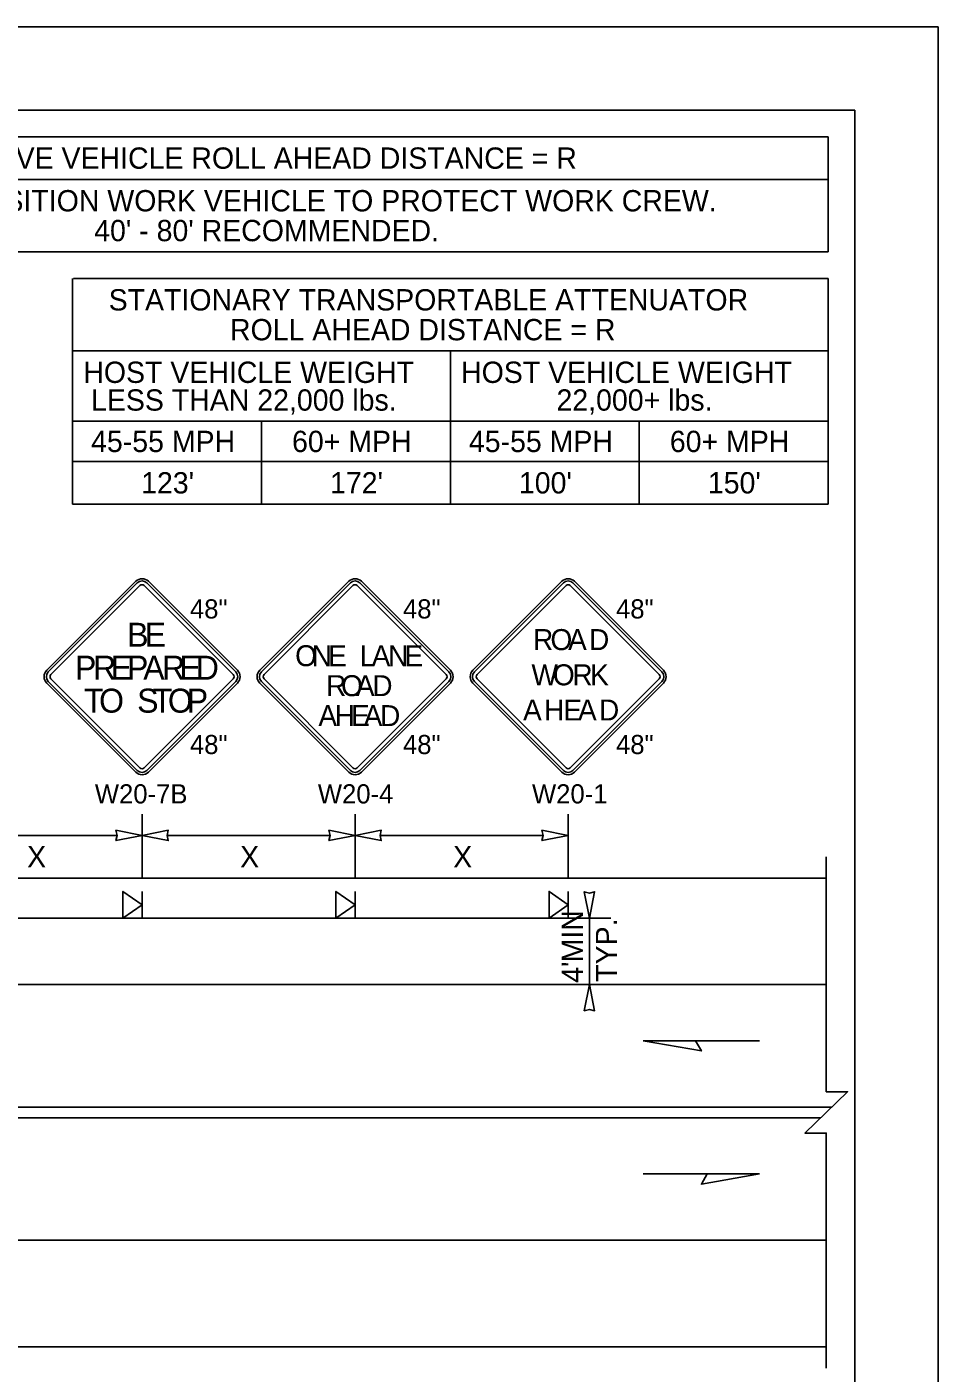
# Model space of a CAD drawing. Extents: x 99999.1 to 100095.7, y 99995 to 100010.7.
# Drawn here: x 100052.64 to 100056.06, y 100005.63 to 100010.69 of the extents above; entities that cross this region are included whole.
import ezdxf

# ---------------------------------------------------------------- set-up
doc = ezdxf.new("R2010")
doc.units = 0
for name, color, linetype in [('RD_ED_ShoulderPavedEdge', 7, 'Continuous'), ('RD_MK_LineDblYellowCenter', 7, 'Continuous'), ('RD_MK_LineEdgeWhite', 7, 'Continuous'), ('SH_GI_PlotLimits', 7, 'Continuous'), ('SH_GI_SheetBorder', 7, 'Continuous'), ('SH_TI_Tables', 7, 'Continuous'), ('TR_SN_ConstructionSigns', 7, 'Continuous'), ('TR_WZ_PortableSignMountBlk-Org', 7, 'Continuous'), ('TR_WZ_WorkZoneDetails', 7, 'Continuous'), ('TR_WZ_WorkZoneTextCurrent', 7, 'Continuous')]:
    doc.layers.add(name, color=color, linetype=linetype)

msp = doc.modelspace()

# ---------------------------------------------------------------- linework, layer by layer
at = {"layer": 'RD_ED_ShoulderPavedEdge'}
for p, q in [((100040.1076, 100007.4923), (100055.6424, 100007.4923)), ((100040.1076, 100005.7323), (100055.6424, 100005.7323))]:
    msp.add_line(p, q, dxfattribs=at)
at = {"layer": 'RD_MK_LineDblYellowCenter'}
for p, q in [((100052.2733, 100006.6323), (100055.6631, 100006.6323)), ((100052.2733, 100006.5923), (100055.6218, 100006.5923))]:
    msp.add_line(p, q, dxfattribs=at)
at = {"layer": 'RD_MK_LineEdgeWhite'}
for p, q in [((100040.1076, 100007.0923), (100055.6424, 100007.0923)), ((100040.1076, 100006.1323), (100055.6424, 100006.1323))]:
    msp.add_line(p, q, dxfattribs=at)
at = {"layer": 'SH_GI_PlotLimits'}
msp.add_lwpolyline([(100039.0625, 99999.6875), (100056.0625, 99999.6875), (100056.0625, 100010.6875), (100039.0625, 100010.6875)], close=True, dxfattribs=at)
at = {"layer": 'SH_GI_SheetBorder'}
for p, q in [((100040, 100010.375), (100055.75, 100010.375)), ((100055.75, 100010.375), (100055.75, 100000))]:
    msp.add_line(p, q, dxfattribs=at)
at = {"layer": 'SH_TI_Tables'}
for p, q in [((100051.4347, 100010.275), (100055.65, 100010.275)), ((100055.65, 100009.843), (100055.65, 100010.275)), ((100051.4347, 100010.115), (100055.65, 100010.115)), ((100051.4347, 100009.843), (100055.65, 100009.843)), ((100052.8126, 100008.896), (100052.8126, 100009.743)), ((100052.8156, 100009.743), (100055.65, 100009.743)), ((100055.65, 100008.896), (100055.65, 100009.743)), ((100052.8126, 100009.471), (100055.65, 100009.471)), ((100054.2313, 100008.896), (100054.2313, 100009.471)), ((100052.8126, 100009.2069), (100054.2313, 100009.2069)), ((100053.5219, 100008.896), (100053.5219, 100009.2069)), ((100054.2313, 100009.2069), (100055.65, 100009.2069)), ((100054.9406, 100008.896), (100054.9406, 100009.2069)), ((100052.8126, 100009.056), (100054.2313, 100009.056)), ((100054.2313, 100009.056), (100055.65, 100009.056)), ((100052.8126, 100008.896), (100055.65, 100008.896))]:
    msp.add_line(p, q, dxfattribs=at)
at = {"layer": 'TR_SN_ConstructionSigns'}
for p, q in [((100053.0495, 100008.6062), (100052.7154, 100008.2721)), ((100053.0555, 100008.6002), (100052.7213, 100008.2661)), ((100052.7313, 100008.2561), (100053.0654, 100008.5903)), ((100053.0813, 100008.5903), (100053.4154, 100008.2561)), ((100053.4254, 100008.2661), (100053.0912, 100008.6002)), ((100053.4313, 100008.2721), (100053.0972, 100008.6062)), ((100053.8495, 100008.6062), (100053.5154, 100008.2721)), ((100053.8555, 100008.6002), (100053.5213, 100008.2661)), ((100053.5313, 100008.2561), (100053.8654, 100008.5903)), ((100053.8813, 100008.5903), (100054.2154, 100008.2561)), ((100054.2254, 100008.2661), (100053.8912, 100008.6002)), ((100054.2313, 100008.2721), (100053.8972, 100008.6062)), ((100054.6495, 100008.6062), (100054.3154, 100008.2721)), ((100054.6555, 100008.6002), (100054.3213, 100008.2661)), ((100054.3313, 100008.2561), (100054.6654, 100008.5903)), ((100054.6813, 100008.5903), (100055.0154, 100008.2561)), ((100055.0254, 100008.2661), (100054.6912, 100008.6002)), ((100055.0313, 100008.2721), (100054.6972, 100008.6062)), ((100053.0654, 100007.9061), (100052.7313, 100008.2402)), ((100053.4154, 100008.2402), (100053.0813, 100007.9061)), ((100053.8654, 100007.9061), (100053.5313, 100008.2402)), ((100054.2154, 100008.2402), (100053.8813, 100007.9061)), ((100054.6654, 100007.9061), (100054.3313, 100008.2402)), ((100055.0154, 100008.2402), (100054.6813, 100007.9061)), ((100052.7154, 100008.2243), (100053.0495, 100007.8902)), ((100052.7213, 100008.2303), (100053.0555, 100007.8962)), ((100053.0912, 100007.8962), (100053.4254, 100008.2303)), ((100053.0972, 100007.8902), (100053.4313, 100008.2243)), ((100053.5154, 100008.2243), (100053.8495, 100007.8902)), ((100053.5213, 100008.2303), (100053.8555, 100007.8962)), ((100053.8912, 100007.8962), (100054.2254, 100008.2303)), ((100053.8972, 100007.8902), (100054.2313, 100008.2243)), ((100054.3154, 100008.2243), (100054.6495, 100007.8902)), ((100054.3213, 100008.2303), (100054.6555, 100007.8962)), ((100054.6912, 100007.8962), (100055.0254, 100008.2303)), ((100054.6972, 100007.8902), (100055.0313, 100008.2243))]:
    msp.add_line(p, q, dxfattribs=at)
for centre, radius, start, end in [((100053.0733, 100008.5823), 0.0338, 45, 135), ((100053.0733, 100008.5823), 0.0253, 45, 135), ((100053.0733, 100008.5823), 0.0113, 45, 135), ((100053.8733, 100008.5823), 0.0338, 45, 135), ((100053.8733, 100008.5823), 0.0253, 45, 135), ((100053.8733, 100008.5823), 0.0113, 45, 135), ((100054.6733, 100008.5823), 0.0338, 45, 135), ((100054.6733, 100008.5823), 0.0253, 45, 135), ((100054.6733, 100008.5823), 0.0113, 45, 135), ((100052.7392, 100008.2482), 0.0338, 135, 225), ((100052.7392, 100008.2482), 0.0253, 135, 225), ((100052.7392, 100008.2482), 0.0113, 135, 225), ((100053.4075, 100008.2482), 0.0113, 315, 45), ((100053.4075, 100008.2482), 0.0253, 315, 45), ((100053.4075, 100008.2482), 0.0338, 315, 45), ((100053.5392, 100008.2482), 0.0338, 135, 225), ((100053.5392, 100008.2482), 0.0253, 135, 225), ((100053.5392, 100008.2482), 0.0113, 135, 225), ((100054.2075, 100008.2482), 0.0113, 315, 45), ((100054.2075, 100008.2482), 0.0253, 315, 45), ((100054.2075, 100008.2482), 0.0338, 315, 45), ((100054.3392, 100008.2482), 0.0338, 135, 225), ((100054.3392, 100008.2482), 0.0253, 135, 225), ((100054.3392, 100008.2482), 0.0113, 135, 225), ((100055.0075, 100008.2482), 0.0113, 315, 45), ((100055.0075, 100008.2482), 0.0253, 315, 45), ((100055.0075, 100008.2482), 0.0338, 315, 45), ((100053.0733, 100007.9141), 0.0338, 225, 315), ((100053.0733, 100007.9141), 0.0253, 225, 315), ((100053.0733, 100007.9141), 0.0113, 225, 315), ((100053.8733, 100007.9141), 0.0338, 225, 315), ((100053.8733, 100007.9141), 0.0253, 225, 315), ((100053.8733, 100007.9141), 0.0113, 225, 315), ((100054.6733, 100007.9141), 0.0338, 225, 315), ((100054.6733, 100007.9141), 0.0253, 225, 315), ((100054.6733, 100007.9141), 0.0113, 225, 315)]:
    msp.add_arc(centre, radius, start, end, dxfattribs=at)
at = {"layer": 'TR_WZ_PortableSignMountBlk-Org'}
for p, q in [((100053.0733, 100007.4422), (100053.0733, 100007.3422)), ((100053.8733, 100007.4422), (100053.8733, 100007.3422)), ((100054.6733, 100007.4422), (100054.6733, 100007.3422))]:
    msp.add_line(p, q, dxfattribs=at)
for points in [[(100053.0733, 100007.3923), (100053.0015, 100007.3422), (100053.0015, 100007.4422)], [(100053.8733, 100007.3923), (100053.8015, 100007.3422), (100053.8015, 100007.4422)], [(100054.6733, 100007.3923), (100054.6015, 100007.3422), (100054.6015, 100007.4422)]]:
    msp.add_lwpolyline(points, close=True, dxfattribs=at)
at = {"layer": 'TR_WZ_WorkZoneDetails'}
for p, q in [((100053.0733, 100007.4923), (100053.0733, 100007.7323)), ((100053.8733, 100007.4923), (100053.8733, 100007.7323)), ((100054.6733, 100007.4921), (100054.6733, 100007.7323)), ((100052.3671, 100007.6523), (100052.9796, 100007.6523)), ((100053.1671, 100007.6523), (100053.7796, 100007.6523)), ((100053.9671, 100007.6523), (100054.5796, 100007.6523)), ((100052.2733, 100007.3422), (100054.6733, 100007.3422)), ((100054.6733, 100007.3422), (100054.8333, 100007.3422)), ((100054.7533, 100007.3422), (100054.7533, 100007.0923)), ((100054.6733, 100007.0923), (100054.8333, 100007.0923)), ((100055.1513, 100006.8816), (100055.3924, 100006.8816)), ((100055.1959, 100006.3816), (100054.9548, 100006.3816))]:
    msp.add_line(p, q, dxfattribs=at)
for points in [[(100053.0733, 100007.6523), (100052.9751, 100007.6331), (100052.9796, 100007.6523), (100052.9751, 100007.6716)], [(100053.0733, 100007.6523), (100053.1716, 100007.6331), (100053.1671, 100007.6523), (100053.1716, 100007.6716)], [(100053.8733, 100007.6523), (100053.7751, 100007.6331), (100053.7796, 100007.6523), (100053.7751, 100007.6716)], [(100053.8733, 100007.6523), (100053.9716, 100007.6331), (100053.9671, 100007.6523), (100053.9716, 100007.6716)], [(100054.6733, 100007.6523), (100054.5751, 100007.6331), (100054.5796, 100007.6523), (100054.5751, 100007.6716)], [(100054.7533, 100007.3422), (100054.7341, 100007.4405), (100054.7533, 100007.436), (100054.7726, 100007.4405)], [(100054.7533, 100007.0923), (100054.7341, 100006.9941), (100054.7533, 100006.9986), (100054.7726, 100006.9941)], [(100054.9548, 100006.8816), (100055.1736, 100006.843), (100055.1513, 100006.8816)], [(100055.3924, 100006.3816), (100055.1736, 100006.343), (100055.1959, 100006.3816)]]:
    msp.add_lwpolyline(points, close=True, dxfattribs=at)
msp.add_lwpolyline([(100055.6424, 100005.6523), (100055.6424, 100006.5349), (100055.5624, 100006.5349), (100055.7225, 100006.6898), (100055.6424, 100006.6898), (100055.6424, 100007.5723)], dxfattribs=at)

# ---------------------------------------------------------------- texts
at = {"layer": 'SH_TI_Tables'}
for s, p in [('PROTECTIVE VEHICLE ROLL AHEAD DISTANCE = R', (100052.0577, 100010.155)), ('STRATEGICALLY POSITION WORK VEHICLE TO PROTECT WORK CREW.', (100051.4984, 100009.995)), ("40' - 80'", (100052.8935, 100009.883)), ('RECOMMENDED.', (100053.297, 100009.883)), ('STATIONARY TRANSPORTABLE ATTENUATOR', (100052.9479, 100009.623)), ('ROLL AHEAD DISTANCE = R', (100053.4035, 100009.511)), ('HOST VEHICLE WEIGHT', (100052.8526, 100009.351)), ('HOST VEHICLE WEIGHT', (100054.2713, 100009.351)), ('LESS THAN 22,000 lbs.', (100052.8817, 100009.2469)), ('22,000+ lbs.', (100054.6295, 100009.2469)), ('45-55 MPH', (100052.8818, 100009.0914)), ('60+ MPH', (100053.6365, 100009.0914)), ('45-55 MPH', (100054.3006, 100009.0914)), ('60+ MPH', (100055.0552, 100009.0914)), ("123'", (100053.0698, 100008.936)), ("172'", (100053.7792, 100008.936)), ("100'", (100054.4885, 100008.936)), ("150'", (100055.1979, 100008.936))]:
    msp.add_text(s, height=0.08, rotation=360, dxfattribs=at).set_placement(p)
at = {"layer": 'TR_SN_ConstructionSigns'}
for s, p in [('48"', (100053.2531, 100008.4667)), ('48"', (100054.0531, 100008.4667)), ('48"', (100054.8531, 100008.4667)), ('48"', (100053.2531, 100007.9576)), ('48"', (100054.0531, 100007.9576)), ('48"', (100054.8531, 100007.9576)), ('W20-7B', (100052.896, 100007.7723)), ('W20-4', (100053.7334, 100007.7723)), ('W20-1', (100054.5375, 100007.7723))]:
    msp.add_text(s, height=0.072, rotation=360, dxfattribs=at).set_placement(p)
for s, height, p in [('B', 0.09, (100053.0175, 100008.3607)), ('E', 0.09, (100053.0832, 100008.3607)), ('R', 0.0788, (100054.5414, 100008.348)), ('O', 0.0788, (100054.6068, 100008.348)), ('A', 0.0788, (100054.673, 100008.348)), ('D', 0.0788, (100054.7517, 100008.348)), ('O', 0.0787, (100053.6481, 100008.2876)), ('N', 0.0787, (100053.7103, 100008.2876)), ('E', 0.0787, (100053.7718, 100008.2876)), ('L', 0.0787, (100053.8907, 100008.2876)), ('A', 0.0787, (100053.9356, 100008.2876)), ('N', 0.0787, (100053.997, 100008.2876)), ('E', 0.0787, (100054.0584, 100008.2876)), ('P', 0.09, (100052.8213, 100008.2369)), ('R', 0.09, (100052.8897, 100008.2369)), ('E', 0.09, (100052.9554, 100008.2369)), ('P', 0.09, (100053.0166, 100008.2369)), ('A', 0.09, (100053.0778, 100008.2369)), ('R', 0.09, (100053.148, 100008.2369)), ('E', 0.09, (100053.2137, 100008.2369)), ('D', 0.09, (100053.2749, 100008.2369)), ('W', 0.0788, (100054.5355, 100008.2158)), ('O', 0.0788, (100054.6159, 100008.2158)), ('R', 0.0788, (100054.6891, 100008.2158)), ('K', 0.0788, (100054.756, 100008.2158)), ('R', 0.0787, (100053.7647, 100008.1751)), ('O', 0.0787, (100053.8206, 100008.1751)), ('A', 0.0787, (100053.8765, 100008.1751)), ('D', 0.0787, (100053.9379, 100008.1751)), ('T', 0.09, (100052.8551, 100008.1132)), ('O', 0.09, (100052.9118, 100008.1132)), ('S', 0.09, (100053.0549, 100008.1132)), ('T', 0.09, (100053.1134, 100008.1132)), ('O', 0.09, (100053.1701, 100008.1132)), ('P', 0.09, (100053.2412, 100008.1132)), ('A', 0.0787, (100053.7355, 100008.0626)), ('H', 0.0787, (100053.797, 100008.0626)), ('E', 0.0787, (100053.8584, 100008.0626)), ('A', 0.0787, (100053.9056, 100008.0626)), ('D', 0.0787, (100053.9671, 100008.0626)), ('A', 0.0788, (100054.504, 100008.0837)), ('H', 0.0788, (100054.5828, 100008.0837)), ('E', 0.0788, (100054.6552, 100008.0837)), ('A', 0.0788, (100054.7104, 100008.0837)), ('D', 0.0788, (100054.7891, 100008.0837))]:
    msp.add_text(s, height=height, dxfattribs=at).set_placement(p)
at = {"layer": 'TR_WZ_WorkZoneTextCurrent'}
for p in [(100052.6416, 100007.5323), (100053.4416, 100007.5323), (100054.2416, 100007.5323)]:
    msp.add_text('X', height=0.08, dxfattribs=at).set_placement(p)
for s, p in [('MIN', (100054.7293, 100007.1754)), ('TYP.', (100054.8573, 100007.1026)), ("4'", (100054.7293, 100007.0989))]:
    msp.add_text(s, height=0.08, rotation=90, dxfattribs=at).set_placement(p)

doc.saveas('drawing.dxf')
